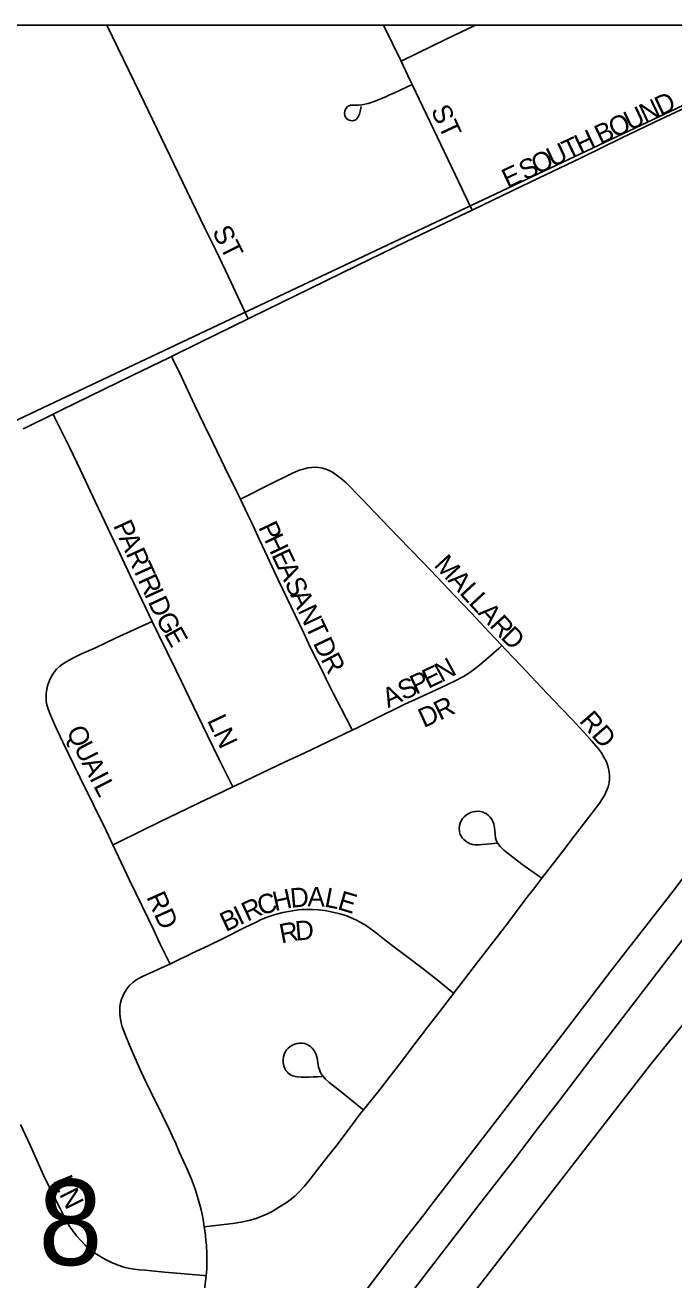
# Model space of a CAD drawing. Extents: x -5.6 to 34, y 0 to 22.
# Drawn here: x 6.458 to 7.127, y 19.608 to 20.9 of the extents above; entities that cross this region are included whole.
import ezdxf

# ---------------------------------------------------------------- set-up
doc = ezdxf.new("R2010")
doc.units = 0
for name, color, linetype in [('GM_X_City_Street', 7, 'Continuous'), ('GM_X_City_Street_Text', 7, 'Continuous'), ('GM_X_Corporation', 7, 'Continuous'), ('GM_X_Interstate_Route', 7, 'Continuous'), ('GM_X_Minor_River', 7, 'Continuous'), ('GM_X_Section', 7, 'Continuous'), ('GM_X_Section_Text', 7, 'Continuous'), ('GM_X_Township', 7, 'Continuous'), ('SH_Data', 7, 'Continuous')]:
    doc.layers.add(name, color=color, linetype=linetype)

msp = doc.modelspace()

# ---------------------------------------------------------------- linework, layer by layer
at = {"layer": 'GM_X_City_Street'}
msp.add_line((6.8456, 20.8627), (6.8276, 20.9), dxfattribs=at)
for points in [[(6.688, 20.5975), (6.6824, 20.6098), (6.668, 20.6409), (6.6551, 20.6674), (6.6435, 20.691), (6.6163, 20.7471), (6.5765, 20.8298), (6.5426, 20.9)], [(6.8456, 20.8627), (6.8627, 20.8712), (6.892, 20.8856), (6.9216, 20.8996), (6.9224, 20.9)], [(6.9188, 20.7095), (6.9607, 20.7297), (6.988, 20.7427), (7.0306, 20.763), (7.0731, 20.7839), (7.1134, 20.8032), (7.1538, 20.8221), (7.1975, 20.8433), (7.241, 20.8649), (7.2671, 20.8774), (7.2799, 20.8835)], [(6.857, 20.8389), (6.8548, 20.8436), (6.8456, 20.8627)], [(6.8044, 20.8163), (6.804, 20.8128), (6.8036, 20.811), (6.8027, 20.8083), (6.8019, 20.8063), (6.8008, 20.8045), (6.7994, 20.8029), (6.7979, 20.802), (6.7959, 20.8014), (6.7935, 20.8016), (6.7911, 20.8026), (6.7891, 20.8043), (6.7878, 20.8065), (6.7873, 20.8089), (6.7877, 20.8114), (6.7889, 20.814), (6.7905, 20.816), (6.7922, 20.817), (6.7937, 20.8174), (6.7951, 20.8175), (6.8017, 20.8174), (6.8051, 20.8178), (6.8116, 20.8194), (6.8179, 20.8214), (6.8271, 20.8251), (6.8301, 20.8262), (6.833, 20.8278), (6.839, 20.8303), (6.8449, 20.8331), (6.857, 20.8389)], [(6.9188, 20.7095), (6.9099, 20.728), (6.9085, 20.731), (6.857, 20.8389)], [(6.688, 20.5975), (6.6917, 20.5993), (6.7364, 20.6212), (6.7998, 20.6522), (6.8506, 20.6767), (6.9067, 20.7037), (6.9188, 20.7095)], [(6.609, 20.5588), (6.6385, 20.5733), (6.688, 20.5975)], [(6.4871, 20.4992), (6.4955, 20.5033), (6.525, 20.5178), (6.5685, 20.5393), (6.6064, 20.5575), (6.609, 20.5588)], [(6.6801, 20.4118), (6.6762, 20.4199), (6.6641, 20.4445), (6.6518, 20.4701), (6.6432, 20.4878), (6.633, 20.5091), (6.6194, 20.5377), (6.6101, 20.5565), (6.609, 20.5588)], [(6.4565, 20.4841), (6.4603, 20.4858), (6.4871, 20.4992)], [(6.5894, 20.2857), (6.5794, 20.3067), (6.5664, 20.3338), (6.5535, 20.3611), (6.54, 20.3892), (6.5305, 20.4094), (6.5155, 20.4415), (6.5041, 20.4653), (6.489, 20.4954), (6.4871, 20.4992)], [(6.9496, 20.2611), (6.9362, 20.2752), (6.9181, 20.2943), (6.901, 20.3124), (6.8829, 20.3314), (6.8683, 20.3465), (6.8428, 20.373), (6.8336, 20.3824), (6.8046, 20.4127), (6.789, 20.4286), (6.7843, 20.4329), (6.7803, 20.436), (6.7749, 20.4395), (6.7716, 20.4412), (6.7682, 20.4426), (6.7646, 20.4436), (6.7609, 20.4443), (6.7571, 20.4446), (6.7534, 20.4445), (6.7497, 20.4441), (6.7449, 20.4428), (6.7401, 20.4412), (6.733, 20.4381), (6.7093, 20.4266), (6.6824, 20.413), (6.6801, 20.4118)], [(6.7954, 20.174), (6.7943, 20.1762), (6.7839, 20.1963), (6.7761, 20.2114), (6.7686, 20.2265), (6.7643, 20.2352), (6.7528, 20.258), (6.7451, 20.2745), (6.7323, 20.301), (6.719, 20.3289), (6.7079, 20.3524), (6.6999, 20.3698), (6.6916, 20.3881), (6.6876, 20.3963), (6.6801, 20.4118)], [(6.5488, 20.0557), (6.5418, 20.0705), (6.5291, 20.0965), (6.515, 20.1247), (6.5032, 20.1496), (6.4973, 20.1614), (6.4889, 20.1792), (6.4847, 20.1888), (6.4824, 20.195), (6.4809, 20.2001), (6.4802, 20.2039), (6.48, 20.2078), (6.4801, 20.2118), (6.4806, 20.2157), (6.4815, 20.2195), (6.4827, 20.2233), (6.4842, 20.2269), (6.4861, 20.2304), (6.4883, 20.2336), (6.4908, 20.2367), (6.4937, 20.2395), (6.4968, 20.2419), (6.5012, 20.2447), (6.5081, 20.2485), (6.5164, 20.2525), (6.5309, 20.2587), (6.5522, 20.2689), (6.5702, 20.2771), (6.5794, 20.2812), (6.5894, 20.2857)], [(6.6724, 20.1157), (6.6699, 20.1204), (6.6582, 20.1437), (6.6463, 20.1684), (6.6275, 20.2075), (6.6194, 20.2241), (6.6137, 20.2359), (6.5957, 20.2724), (6.5894, 20.2857)], [(6.7954, 20.174), (6.8003, 20.1763), (6.8168, 20.1844), (6.8497, 20.2006), (6.8639, 20.2073), (6.8722, 20.2111), (6.8864, 20.2176), (6.9006, 20.2243), (6.9099, 20.2291), (6.9164, 20.2333), (6.9217, 20.2372), (6.9268, 20.2412), (6.9338, 20.2472), (6.9466, 20.2584), (6.9496, 20.2611)], [(6.9907, 20.0214), (6.9994, 20.0325), (7.0123, 20.0492), (7.0241, 20.0648), (7.0424, 20.0889), (7.0504, 20.0992), (7.0526, 20.1024), (7.0551, 20.1067), (7.0572, 20.1113), (7.059, 20.1156), (7.0599, 20.1196), (7.0603, 20.1235), (7.0603, 20.1272), (7.06, 20.1309), (7.059, 20.1357), (7.0579, 20.1393), (7.0565, 20.1428), (7.0547, 20.1462), (7.0521, 20.1505), (7.0491, 20.1546), (7.0423, 20.1625), (7.037, 20.1683), (7.022, 20.1848), (7.0111, 20.1961), (7.0029, 20.2045), (6.9904, 20.218), (6.9696, 20.24), (6.9533, 20.2571), (6.9496, 20.2611)], [(6.6724, 20.1157), (6.6818, 20.1201), (6.6948, 20.1263), (6.7019, 20.1297), (6.7256, 20.141), (6.7458, 20.1504), (6.7954, 20.174)], [(6.5488, 20.0557), (6.5513, 20.0569), (6.579, 20.0706), (6.5979, 20.0797), (6.6251, 20.0928), (6.6392, 20.0997), (6.6557, 20.1077), (6.6724, 20.1157)], [(6.9907, 20.0214), (6.9887, 20.0228), (6.9795, 20.0295), (6.9702, 20.0359), (6.9609, 20.0431), (6.9578, 20.0456), (6.9517, 20.0505), (6.9488, 20.0531), (6.9479, 20.054), (6.9463, 20.0559), (6.9448, 20.0581), (6.9438, 20.0605), (6.9431, 20.063), (6.9425, 20.0669), (6.9419, 20.0735), (6.9411, 20.0773), (6.9402, 20.0798), (6.939, 20.0821), (6.9375, 20.0842), (6.9357, 20.0861), (6.9336, 20.0877), (6.9313, 20.0889), (6.9301, 20.0894), (6.9275, 20.0901), (6.925, 20.0904), (6.9223, 20.0903), (6.9198, 20.0898), (6.9173, 20.089), (6.9149, 20.0879), (6.9127, 20.0865), (6.9107, 20.0848), (6.909, 20.0828), (6.9076, 20.0806), (6.9066, 20.0782), (6.9059, 20.0756), (6.9056, 20.073), (6.9058, 20.0704), (6.906, 20.0691), (6.9067, 20.0666), (6.9073, 20.0654), (6.9087, 20.0632), (6.9104, 20.0612), (6.9123, 20.0595), (6.9145, 20.0581), (6.9169, 20.057), (6.9194, 20.0563), (6.922, 20.0559), (6.926, 20.0559), (6.9291, 20.0562), (6.9336, 20.0565), (6.9378, 20.0569), (6.9443, 20.0575)], [(6.6076, 19.9331), (6.607, 19.9344), (6.5972, 19.9544), (6.5905, 19.9686), (6.5854, 19.9792), (6.566, 20.0194), (6.5488, 20.0557)], [(6.8999, 19.9032), (6.9003, 19.9037), (6.9051, 19.9099), (6.9075, 19.913), (6.9155, 19.9234), (6.9234, 19.9338), (6.9459, 19.9628), (6.9563, 19.9763), (6.9753, 20.0015), (6.9833, 20.0119), (6.9907, 20.0214)], [(6.6076, 19.9331), (6.608, 19.9332), (6.6151, 19.9366), (6.6186, 19.9384), (6.6245, 19.9412), (6.6292, 19.9435), (6.635, 19.9463), (6.6468, 19.9519), (6.6631, 19.9598), (6.6841, 19.9702), (6.697, 19.9766), (6.7014, 19.9789), (6.7077, 19.9815), (6.7161, 19.984), (6.724, 19.986), (6.7319, 19.9877), (6.7396, 19.9888), (6.7435, 19.9892), (6.7501, 19.9894), (6.754, 19.9893), (6.7605, 19.9888), (6.7671, 19.9881), (6.7735, 19.987), (6.7812, 19.9853), (6.7887, 19.9829), (6.7936, 19.9811), (6.7996, 19.9784), (6.8065, 19.9746), (6.8099, 19.9725), (6.8163, 19.968), (6.8204, 19.9648), (6.8307, 19.9566), (6.838, 19.951), (6.8516, 19.9407), (6.8683, 19.928), (6.8828, 19.9168), (6.8981, 19.9046), (6.8999, 19.9032)], [(6.6429, 19.6624), (6.6424, 19.6656), (6.641, 19.6739), (6.6397, 19.68), (6.638, 19.686), (6.6366, 19.6911), (6.6334, 19.7011), (6.6303, 19.7097), (6.6253, 19.7218), (6.6216, 19.7302), (6.6172, 19.7398), (6.6135, 19.7482), (6.6098, 19.7562), (6.6066, 19.763), (6.5998, 19.7772), (6.5946, 19.7878), (6.5909, 19.7951), (6.5875, 19.8022), (6.5835, 19.8104), (6.5779, 19.8222), (6.5701, 19.84), (6.5658, 19.8497), (6.5614, 19.8605), (6.5596, 19.865), (6.5585, 19.8683), (6.5578, 19.8712), (6.5567, 19.8764), (6.556, 19.8816), (6.5558, 19.8855), (6.556, 19.8894), (6.5566, 19.8933), (6.5578, 19.897), (6.5593, 19.9006), (6.5605, 19.903), (6.5617, 19.9053), (6.5639, 19.9085), (6.5664, 19.9115), (6.5693, 19.9142), (6.5724, 19.9165), (6.5758, 19.9186), (6.5805, 19.9209), (6.5901, 19.9251), (6.602, 19.9305), (6.6076, 19.9331)], [(6.8069, 19.7828), (6.8128, 19.7901), (6.8217, 19.8012), (6.8265, 19.8074), (6.8345, 19.8177), (6.8465, 19.8332), (6.8576, 19.8478), (6.8679, 19.8613), (6.8734, 19.8685), (6.8852, 19.8839), (6.8999, 19.9032)], [(6.8069, 19.7828), (6.8042, 19.785), (6.789, 19.7973), (6.7792, 19.8052), (6.7717, 19.8112), (6.7678, 19.8147), (6.7657, 19.8168), (6.7643, 19.8185), (6.7633, 19.8201), (6.7624, 19.822), (6.7615, 19.8244), (6.7607, 19.8269), (6.7593, 19.836), (6.7582, 19.8398), (6.7575, 19.8413), (6.7557, 19.8444), (6.7541, 19.8464), (6.7522, 19.8482), (6.75, 19.8496), (6.7489, 19.8502), (6.7464, 19.8511), (6.7438, 19.8516), (6.7412, 19.8517), (6.7386, 19.8514), (6.7361, 19.8507), (6.7337, 19.8497), (6.7314, 19.8483), (6.7295, 19.8466), (6.7278, 19.8446), (6.7264, 19.8424), (6.7254, 19.84), (6.7246, 19.8375), (6.7243, 19.8349), (6.7242, 19.8322), (6.7245, 19.8296), (6.7252, 19.8271), (6.7262, 19.8247), (6.7269, 19.8236), (6.7286, 19.8216), (6.7295, 19.8207), (6.7316, 19.8191), (6.734, 19.818), (6.7365, 19.8172), (6.7391, 19.8168), (6.7429, 19.8166), (6.7461, 19.8167), (6.7509, 19.8167), (6.7555, 19.8169), (6.7597, 19.8171), (6.764, 19.8174)], [(6.6429, 19.6624), (6.6454, 19.6627), (6.6723, 19.6658), (6.6825, 19.6677), (6.6901, 19.6694), (6.6963, 19.6712), (6.7023, 19.6734), (6.7082, 19.676), (6.7128, 19.6783), (6.7206, 19.6829), (6.7272, 19.6871), (6.7313, 19.6901), (6.7362, 19.6942), (6.7409, 19.6987), (6.7462, 19.7043), (6.7519, 19.7114), (6.7623, 19.7248), (6.771, 19.7359), (6.7784, 19.7453), (6.7881, 19.7578), (6.8037, 19.779), (6.8069, 19.7828)], [(6.4537, 19.7677), (6.4634, 19.7464), (6.4788, 19.7126), (6.494, 19.682), (6.4994, 19.6716), (6.5013, 19.6681), (6.5046, 19.6625), (6.5074, 19.6582), (6.5114, 19.6531), (6.5157, 19.6483), (6.5203, 19.6437), (6.5252, 19.6395), (6.5293, 19.6362), (6.5336, 19.6333), (6.538, 19.6305), (6.5427, 19.628), (6.5474, 19.6258), (6.5509, 19.6243), (6.5543, 19.623), (6.5591, 19.6214), (6.5613, 19.6207), (6.5662, 19.6196), (6.5706, 19.6188), (6.5759, 19.6183), (6.5819, 19.6177), (6.5885, 19.6172), (6.6019, 19.6159), (6.6186, 19.6144), (6.6424, 19.6122), (6.6448, 19.612)], [(6.6448, 19.612), (6.6455, 19.6188), (6.6457, 19.628), (6.6457, 19.6345), (6.6452, 19.6436), (6.6447, 19.6491), (6.6438, 19.6565), (6.6429, 19.6624)], [(6.6431, 19.598), (6.6448, 19.612)]]:
    msp.add_lwpolyline(points, dxfattribs=at)
at = {"layer": 'GM_X_Corporation'}
msp.add_lwpolyline([(8.2067, 20.9), (4.0671, 20.9)], dxfattribs=at)
at = {"layer": 'GM_X_Interstate_Route'}
for points in [[(6.4434, 19.1203), (6.5045, 19.1998), (6.6774, 19.4249), (6.728, 19.4903), (6.7458, 19.5147), (6.7571, 19.5292), (6.7812, 19.5604), (6.8077, 19.5946), (6.8489, 19.6491), (6.8692, 19.6749), (6.8764, 19.6843), (6.9676, 19.803), (6.9901, 19.832), (7.0116, 19.8603), (7.0636, 19.928), (7.1256, 20.0079), (7.151, 20.0413), (7.1916, 20.0946), (7.2051, 20.1124), (7.2499, 20.1707), (7.2925, 20.2258), (7.3849, 20.342)], [(6.5864, 19.2428), (6.597, 19.2566), (6.6321, 19.3025), (6.6423, 19.3162), (6.7111, 19.4057), (6.7472, 19.4525), (6.7679, 19.4797), (6.8249, 19.5535), (6.8521, 19.5889), (6.9266, 19.6857), (6.9627, 19.7324), (6.9874, 19.7648), (7.0098, 19.794), (7.0433, 19.8378), (7.0866, 19.894), (7.1599, 19.99), (7.2017, 20.0441), (7.2216, 20.0702), (7.2411, 20.0949), (7.2619, 20.122), (7.3092, 20.1834), (7.3458, 20.2314), (7.4003, 20.3021)]]:
    msp.add_lwpolyline(points, dxfattribs=at)
at = {"layer": 'GM_X_Minor_River'}
msp.add_lwpolyline([(8.5297, 15.0523), (8.2755, 15.5636), (7.9273, 16.2717), (7.6894, 16.7524), (7.3893, 17.3541), (7.1716, 17.7937), (6.9143, 18.3107), (6.6663, 18.81), (6.5263, 19.0874), (6.6472, 19.2446), (6.7802, 19.4137), (6.9563, 19.6407), (7.1015, 19.8281), (7.228, 19.9844), (7.2483, 20.0122), (7.2596, 20.0201), (7.2772, 20.0231), (7.3001, 20.0228)], dxfattribs=at)
at = {"layer": 'GM_X_Section'}
msp.add_lwpolyline([(7.5006, 20.9), (7.2498, 20.9), (7.2609, 20.8761), (5.343, 19.9706), (5.3166, 18.9352), (7.4578, 18.9294)], close=True, dxfattribs=at)
at = {"layer": 'GM_X_Township'}
msp.add_lwpolyline([(3.0636, 14.1), (8.9, 14.1), (8.9, 20.9), (2.1, 20.9), (2.1, 16.9108), (2.7242, 16.8707), (3.1388, 16.8616), (3.0745, 14.7121)], close=True, dxfattribs=at)
at = {"layer": 'SH_Data'}
msp.add_line((2.1, 20.9), (8.9, 20.9), dxfattribs=at)

# ---------------------------------------------------------------- texts
at = {"layer": 'GM_X_City_Street_Text'}
for s, rotation, p in [('ST', 295.0177, (6.876, 20.8124)), ('N', 25.3431, (7.0971, 20.7986)), ('D', 25.314, (7.113, 20.8061)), ('O', 25.314, (7.0653, 20.7835)), ('U', 25.3362, (7.0812, 20.791)), ('H', 25.3431, (7.0303, 20.767)), ('B', 25.333, (7.051, 20.7767)), ('U', 25.314, (7.0016, 20.7534)), ('T', 25.342, (7.0176, 20.7609)), ('O', 25.3313, (6.9857, 20.7459)), ('E', 25.3189, (6.9555, 20.7316)), ('S', 25.3189, (6.973, 20.7398)), ('ST', 296.5651, (6.6507, 20.6876)), ('P', 294.4756, (6.5487, 20.3847)), ('P', 295.2942, (6.6983, 20.383)), ('A', 294.453, (6.5545, 20.3719)), ('H', 295.2651, (6.7043, 20.3703)), ('R', 294.4724, (6.5618, 20.3559)), ('E', 295.279, (6.7118, 20.3544)), ('M', 312.6425, (6.8787, 20.3433)), ('T', 294.4791, (6.5684, 20.3415)), ('A', 295.2744, (6.7178, 20.3417)), ('R', 294.458, (6.5742, 20.3287)), ('S', 295.279, (6.7253, 20.3258)), ('A', 312.6586, (6.8931, 20.3278)), ('L', 312.643, (6.905, 20.3148)), ('I', 294.4556, (6.5808, 20.3142)), ('A', 295.2651, (6.7313, 20.313)), ('L', 312.663, (6.9145, 20.3045)), ('D', 294.8982, (6.5845, 20.3061)), ('N', 295.2858, (6.7388, 20.2971)), ('A', 312.6501, (6.9241, 20.2941)), ('G', 298.107, (6.5924, 20.289)), ('T', 295.2942, (6.7464, 20.2812)), ('R', 312.6298, (6.936, 20.2812)), ('E', 299.0339, (6.6009, 20.2732)), ('D', 314.776, (6.9473, 20.2689)), ('D', 295.2809, (6.7546, 20.2637)), ('R', 297.8136, (6.7626, 20.2469)), ('E', 25.5632, (6.8736, 20.2163)), ('N', 28.5356, (6.8873, 20.2228)), ('S', 25.5324, (6.8482, 20.2041)), ('P', 25.5558, (6.8609, 20.2102)), ('A', 25.5582, (6.8323, 20.1965)), ('D', 24.3553, (6.8691, 20.176)), ('R', 26.1188, (6.8857, 20.1835)), ('LN', 295.2018, (6.6455, 20.1841)), ('RD', 310.9138, (7.0284, 20.183)), ('Q', 292.4955, (6.5008, 20.1738)), ('U', 297.0332, (6.5082, 20.1559)), ('A', 297.23, (6.5163, 20.1402)), ('I', 297.1906, (6.5243, 20.1245)), ('L', 297.2292, (6.5283, 20.1167)), ('RD', 293.9693, (6.583, 20.0022)), ('C', 16.9063, (6.701, 19.9829)), ('H', 12.2443, (6.7157, 19.9874)), ('D', 5.0559, (6.7322, 19.991)), ('A', 359.0164, (6.7492, 19.9926)), ('L', 348.8348, (6.7659, 19.9924)), ('E', 343.2327, (6.7792, 19.9898)), ('B', 25.4028, (6.6651, 19.9659)), ('I', 25.3919, (6.6794, 19.9727)), ('R', 24.9465, (6.6873, 19.9765)), ('D', 5.143, (6.7374, 19.9571)), ('R', 11.2671, (6.7224, 19.9541)), ('L', 292.5421, (6.4872, 19.7104)), ('N', 296.3802, (6.4932, 19.6961))]:
    msp.add_text(s, height=0.02, rotation=rotation, dxfattribs=at).set_placement(p)
at = {"layer": 'GM_X_Section_Text'}
msp.add_text('8', height=0.0884, rotation=0, dxfattribs=at).set_placement((6.4722, 19.623))

doc.saveas('drawing.dxf')
